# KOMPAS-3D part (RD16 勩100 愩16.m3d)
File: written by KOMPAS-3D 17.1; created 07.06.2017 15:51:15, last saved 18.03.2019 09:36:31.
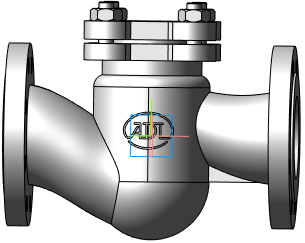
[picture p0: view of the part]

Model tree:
1. Операция без истории:2  (labels: Сталь 20  ГОСТ 1050-88)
